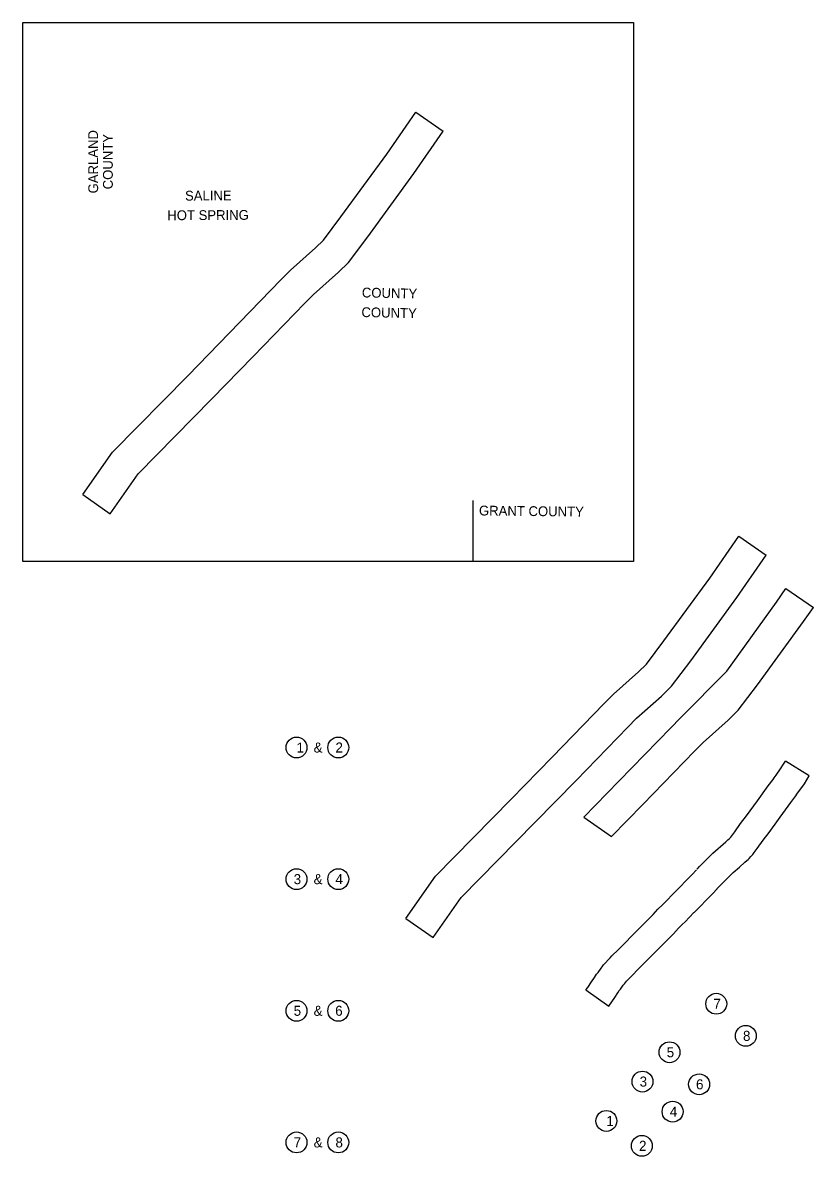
# Model space of a CAD drawing. Extents: x -984 to 3998, y 83 to 2143.
# Drawn here: x -984 to -37, y 708 to 2064 of the extents above; entities that cross this region are included whole.
import ezdxf

# ---------------------------------------------------------------- set-up
doc = ezdxf.new("R2010")
doc.units = 0
for name, color, linetype in [('Level 13', 7, 'Continuous'), ('Level 2', 7, 'Continuous'), ('Level 5', 7, 'Continuous'), ('Level 57', 7, 'Continuous')]:
    doc.layers.add(name, color=color, linetype=linetype)

msp = doc.modelspace()

# ---------------------------------------------------------------- linework, layer by layer
at = {"layer": 'Level 2'}
for p, q in [((-513.1, 1957.2), (-480.2, 1934.4)), ((-911.7, 1499.7), (-879, 1476.7)), ((-126.6, 1449.9), (-93.7, 1427.2)), ((-70.3, 1387.1), (-37.4, 1364.3)), ((-42.2, 1163.2), (-70.8, 1180.7)), ((-117.5, 1115.1), (-104.2, 1133.3)), ((-312.1, 1113.6), (-279, 1090.3)), ((-90.4, 1095.4), (-79.2, 1110.8)), ((-152.9, 1027.7), (-150.1, 1030.5)), ((-525.2, 992.5), (-492.5, 969.4)), ((-309.5, 906.8), (-282.1, 887.4))]:
    msp.add_line(p, q, dxfattribs=at)
for points in [[(-911.7, 1499.7), (-876.1, 1550.3), (-785.7, 1642.2), (-736.4, 1692.7), (-674.4, 1756.7), (-663, 1768.2), (-633.1, 1794.9), (-623.7, 1803.9), (-602.8, 1831.9), (-547.9, 1906.9), (-513.1, 1957.2)], [(-879, 1476.7), (-845.3, 1524.5), (-757.1, 1614.2), (-707.8, 1664.9), (-645.9, 1728.6), (-635.4, 1739.1), (-605.8, 1765.6), (-593.6, 1777.4), (-570.6, 1808.1), (-515.3, 1883.7), (-480.2, 1934.4)], [(-525.2, 992.5), (-489.6, 1043), (-399.1, 1135), (-349.9, 1185.5), (-287.9, 1249.4), (-276.5, 1260.9), (-246.6, 1287.6), (-237.2, 1296.7), (-216.3, 1324.6), (-161.4, 1399.6), (-126.6, 1449.9)], [(-492.5, 969.4), (-458.7, 1017.3), (-370.6, 1107), (-321.2, 1157.6), (-259.3, 1221.4), (-248.9, 1231.9), (-219.3, 1258.3), (-207.1, 1270.2), (-184.1, 1300.8), (-128.8, 1376.4), (-93.7, 1427.2)], [(-312.1, 1113.6), (-270.1, 1156.7), (-208.1, 1220.6), (-196.7, 1232.1), (-140.8, 1288.3), (-81.6, 1370.8), (-70.3, 1387.1)], [(-279, 1090.3), (-241.4, 1128.8), (-179.5, 1192.6), (-169.1, 1203.1), (-139.5, 1229.5), (-127.3, 1241.4), (-104.3, 1272), (-49, 1347.6), (-37.4, 1364.3)], [(-79.2, 1167.8), (-70.8, 1180.7)], [(-104.2, 1133.3), (-91.3, 1150.9), (-85.6, 1158.8), (-84.2, 1160.7), (-81.9, 1163.9), (-79.6, 1167.3), (-79.2, 1167.8)], [(-79.2, 1110.8), (-77.2, 1113.6), (-64.3, 1131.1), (-58.5, 1139), (-57.1, 1141), (-48.1, 1153.5)], [(-48.1, 1153.5), (-42.2, 1163.2)], [(-157.5, 1070.3), (-142, 1084.1), (-139.7, 1086.4), (-137.7, 1088.1), (-137.6, 1088.2), (-137.3, 1088.6), (-136.2, 1089.8), (-135, 1091.3), (-131.4, 1096.2), (-124.4, 1105.8), (-117.4, 1115.2)], [(-133.2, 1047.2), (-125.9, 1053.7), (-119.2, 1059.6), (-117.1, 1061.6), (-115.5, 1063), (-114.1, 1064.3), (-112.2, 1066.3), (-110, 1068.9), (-108.4, 1071.1), (-104.5, 1076.2), (-97.4, 1085.9), (-90.4, 1095.3)], [(-176.5, 1051.4), (-173.5, 1054.5), (-160.1, 1068), (-157.5, 1070.3)], [(-204.2, 1022.7), (-182.5, 1045), (-177.2, 1050.7)], [(-150, 1030.6), (-149.6, 1031), (-136.9, 1043.8), (-133.2, 1047.2)], [(-270.5, 955.4), (-246.7, 979.4), (-238.6, 987.5), (-228.9, 997.2), (-223.3, 1003.5), (-218.1, 1008.8), (-214.4, 1012.4), (-204.2, 1022.8)], [(-180.2, 999.3), (-158.1, 1022), (-152.5, 1028)], [(-244.1, 934.4), (-234.3, 944.3), (-222.9, 955.8), (-214.9, 963.9), (-204.7, 974.1), (-198.8, 980.6), (-194.5, 985.1), (-190.9, 988.5), (-180.3, 999.3)], [(-302.9, 916.4), (-299.3, 921.9), (-296.7, 925.7), (-295, 927.9), (-291.5, 932.7), (-290, 934.6), (-288.4, 936.7), (-286.2, 939.3), (-283, 942.8), (-280.7, 945.4), (-278.5, 947.5), (-270.5, 955.4)], [(-275, 897.8), (-271.4, 903.4), (-269.6, 906), (-268.2, 907.7), (-264.8, 912.4), (-263.4, 914.2), (-262.1, 915.9), (-261, 917.3), (-258.3, 920.3), (-256.8, 921.8), (-255.2, 923.3), (-246.1, 932.4), (-244.1, 934.4)], [(-309.5, 906.8), (-307.3, 909.9), (-302.9, 916.4)], [(-282.1, 887.4), (-275, 897.8)]]:
    msp.add_lwpolyline(points, dxfattribs=at)
for centre in [(-655.9, 1196.9), (-605.9, 1196.9), (-655.9, 1039.4), (-605.9, 1039.4), (-153.6, 890.3), (-655.9, 881.9), (-605.9, 881.9), (-118.2, 851.9), (-209.5, 832.3), (-241.9, 797.2), (-174.1, 793.9), (-205.8, 761.2), (-285.1, 750.1), (-655.9, 724.4), (-605.9, 724.4), (-242.6, 720.3)]:
    msp.add_circle(centre, 12.5, dxfattribs=at)
at = {"layer": 'Level 5'}
msp.add_lwpolyline([(-444.8, 1492.3), (-444.8, 1432.7), (-444.9, 1419.5)], dxfattribs=at)
at = {"layer": 'Level 57'}
msp.add_lwpolyline([(-983.6, 2064.2), (-252.5, 2064.2), (-252.5, 1419.5), (-983.6, 1419.5)], close=True, dxfattribs=at)

# ---------------------------------------------------------------- texts
at = {"layer": 'Level 13'}
for s, height, rotation, p in [('GARLAND', 11.73, 90.1584, (-893.3, 1859.9)), ('COUNTY', 11.73, 90.1584, (-875.7, 1864.8)), ('SALINE', 11.73, 0.3025, (-789.3, 1851.3)), ('HOT SPRING', 11.73, 0.3025, (-810.5, 1827.8)), ('COUNTY', 11.73, 358.7542, (-577.8, 1735.5)), ('COUNTY', 11.73, 358.7542, (-578.3, 1712)), ('GRANT COUNTY', 11.733, 359.3513, (-437.6, 1474.6))]:
    msp.add_text(s, height=height, rotation=rotation, dxfattribs=at).set_placement(p)
at = {"layer": 'Level 2'}
for s, p in [('1', (-655.9, 1190.9)), ('&', (-635.4, 1190.9)), ('2', (-609.3, 1190.9)), ('3', (-659.3, 1033.4)), ('&', (-635.4, 1033.4)), ('4', (-609.3, 1033.4)), ('7', (-157, 884.3)), ('5', (-659.3, 875.9)), ('&', (-635.4, 875.9)), ('6', (-609.6, 875.9)), ('8', (-121.6, 845.9)), ('5', (-212.9, 826.3)), ('3', (-245.3, 791.2)), ('6', (-177.8, 787.9)), ('4', (-209.2, 755.2)), ('1', (-285.1, 744.1)), ('7', (-659.3, 718.4)), ('&', (-635.4, 718.4)), ('8', (-609.3, 718.4)), ('2', (-246, 714.3))]:
    msp.add_text(s, height=12, dxfattribs=at).set_placement(p)

doc.saveas('drawing.dxf')
